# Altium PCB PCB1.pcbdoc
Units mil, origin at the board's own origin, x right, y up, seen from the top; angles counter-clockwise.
Board outline 3300 x 2850 mil, 2 copper layers (Top Layer, Bottom Layer), stack 62.206 mil thick; 39 components, 28 nets, 169 pads, 54 vias.
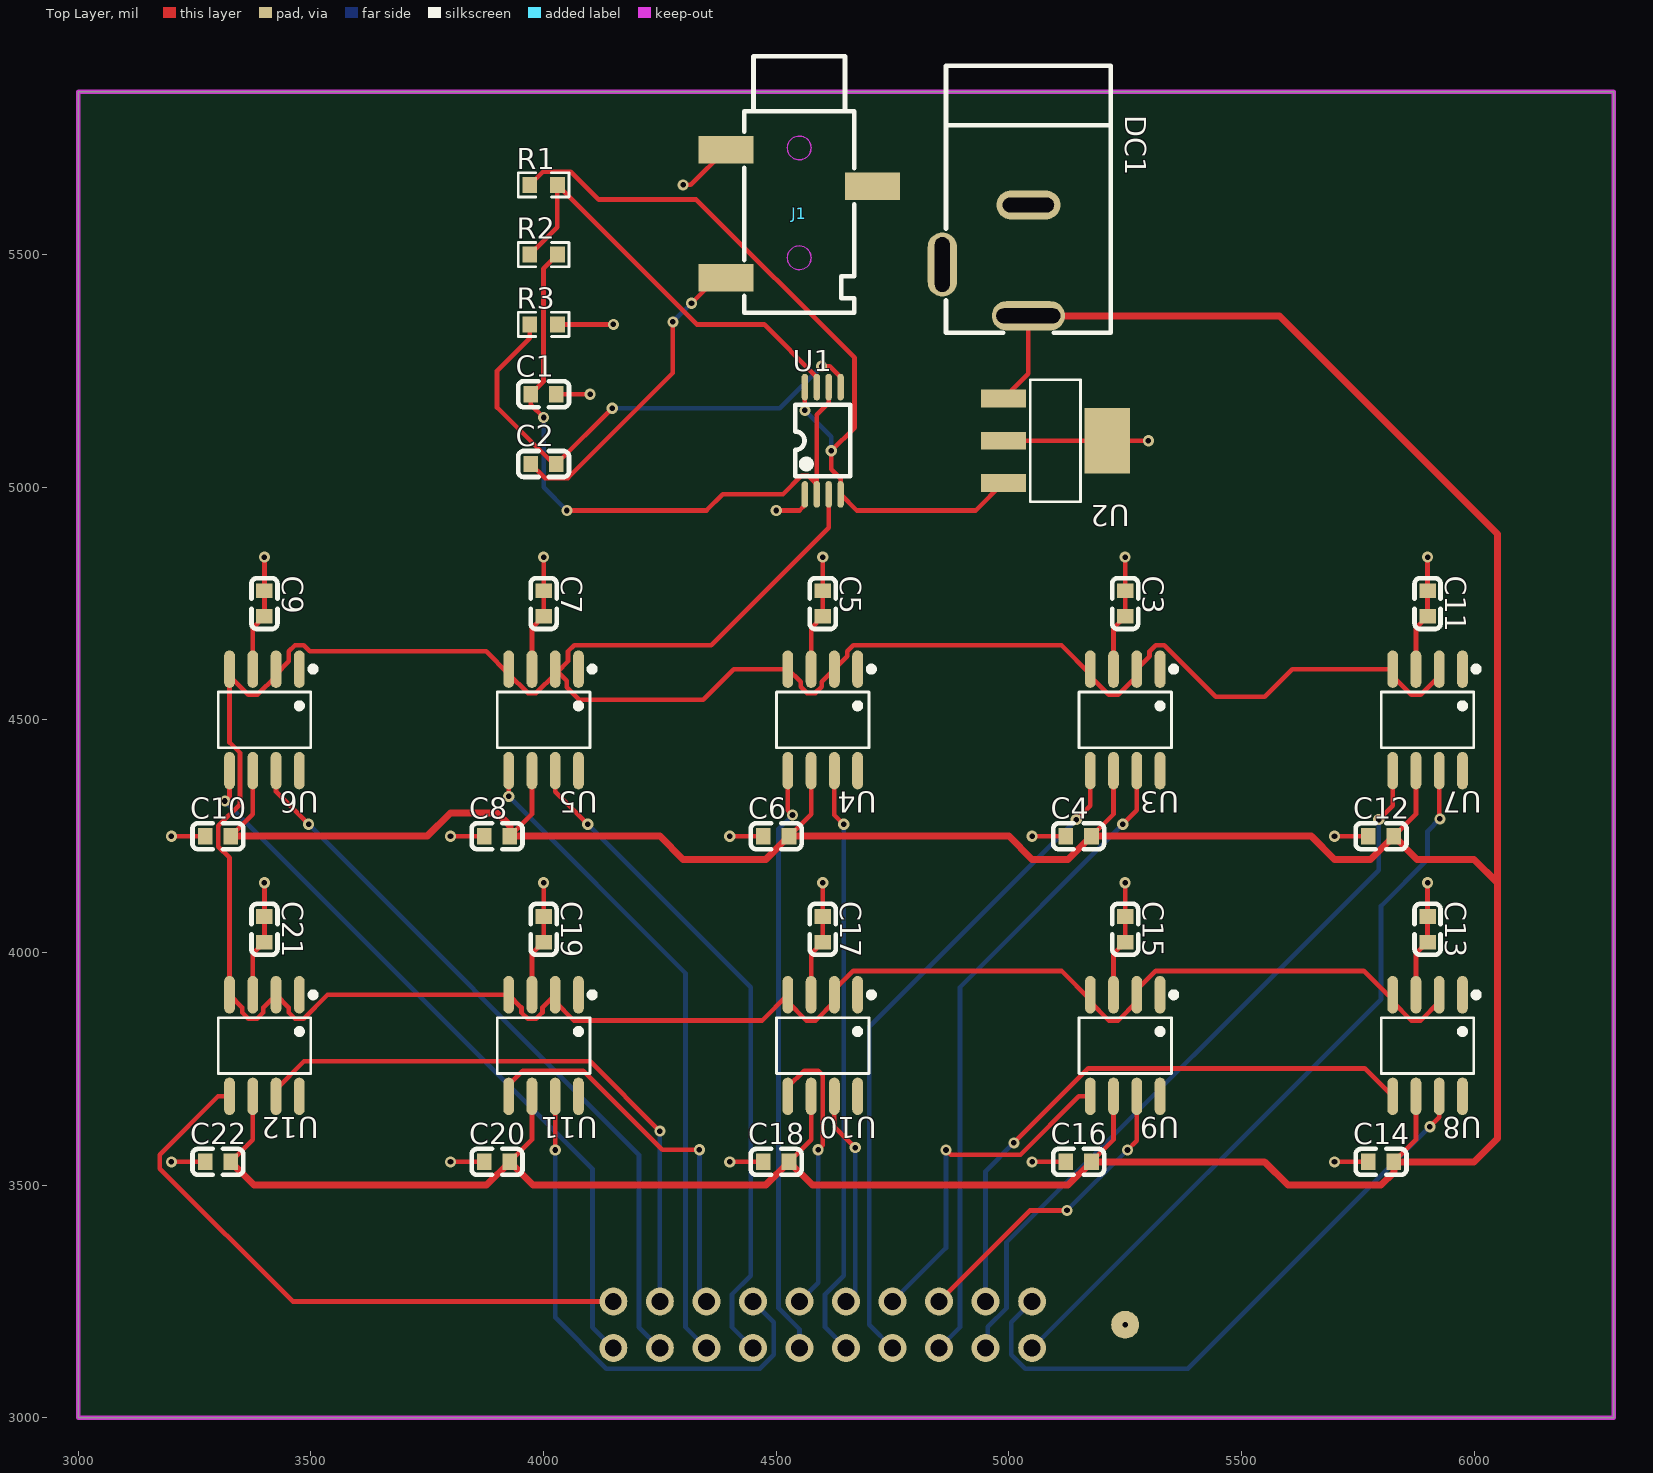
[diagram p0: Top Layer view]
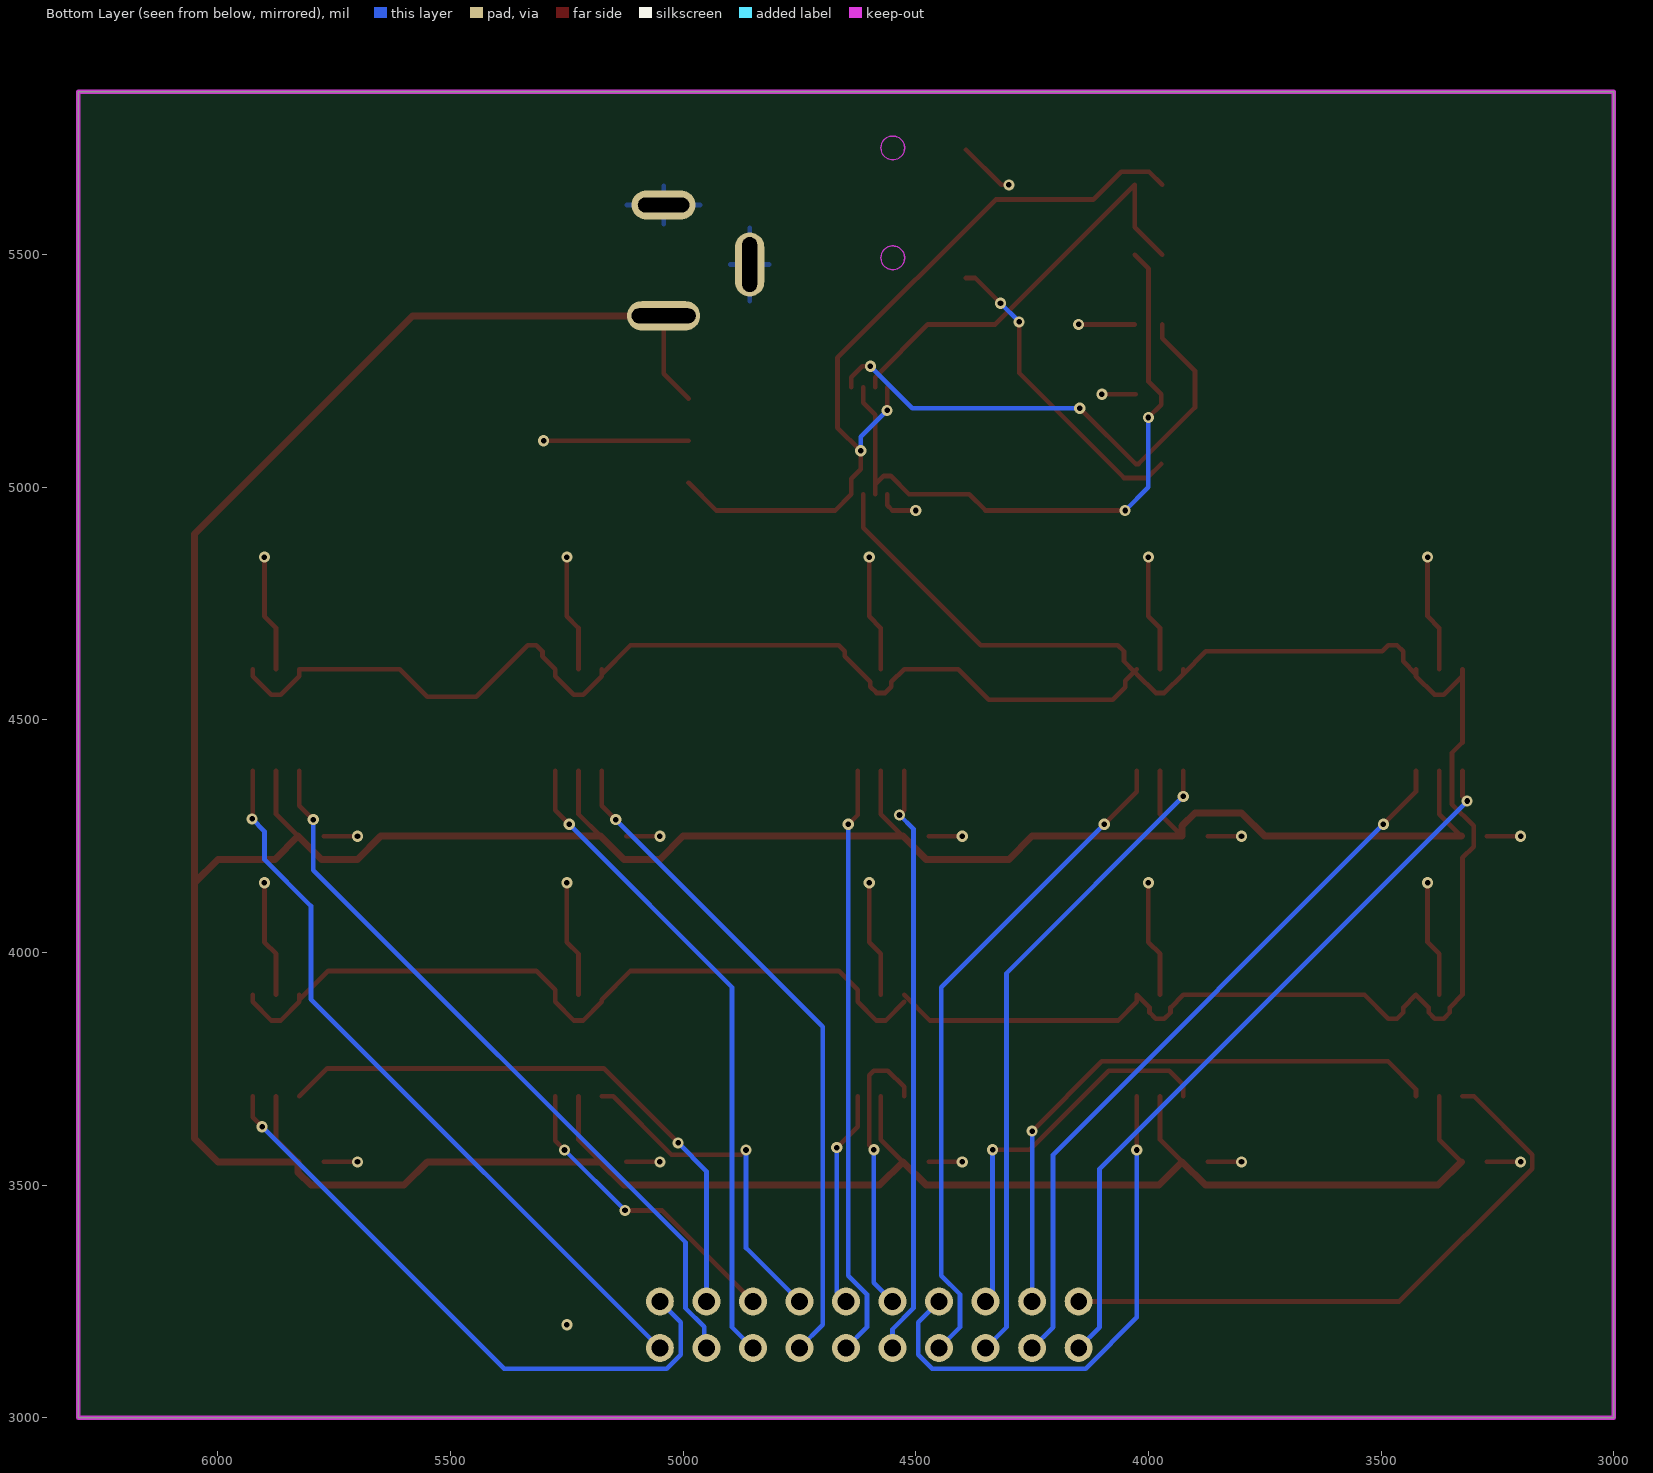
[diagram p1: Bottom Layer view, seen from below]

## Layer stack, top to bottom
Top Solder Mask Layer: solder mask 0.394, Dk 3.3
Top Layer: signal copper 1.379
Dielectric1: surface 59.449, FR4, Dk 4.5
Bottom Layer: signal copper 1.378
Bottom Solder Mask Layer: solder mask 0.394, Dk 3.3

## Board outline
3000,5850 6300,5850 6300,3000 3000,3000

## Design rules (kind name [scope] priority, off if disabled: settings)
BoardOutlineClearance copperThickness1oz [All] p0: genericclearance=10 ignorepadtopadclearanceinfootprint=FALSE except(0: Arc-SplitContinuation Track-SplitContinuation SMDPad-SplitContinuation THPad-SplitContinuation Via-SplitContinuation Fill-SplitContinuation Poly-SplitContinuation Region-SplitContinuation Text-SplitContinuation)
BoardOutlineClearance copperThickness2oz [All] p0: genericclearance=10 ignorepadtopadclearanceinfootprint=FALSE except(0: Arc-SplitContinuation Track-SplitContinuation SMDPad-SplitContinuation THPad-SplitContinuation Via-SplitContinuation Fill-SplitContinuation Poly-SplitContinuation Region-SplitContinuation Text-SplitContinuation)
BoardOutlineClearance otherClearance [All] p0: genericclearance=10 ignorepadtopadclearanceinfootprint=FALSE except(0: Arc-SplitContinuation Track-SplitContinuation SMDPad-SplitContinuation THPad-SplitContinuation Via-SplitContinuation Fill-SplitContinuation Poly-SplitContinuation Region-SplitContinuation Text-SplitContinuation)
Clearance copperThickness1oz [All] p1: gap=7 ignorepadtopadclearanceinfootprint=FALSE
Clearance copperThickness2oz [All] p1: gap=7 ignorepadtopadclearanceinfootprint=FALSE
Clearance otherClearance [All] p1: gap=7 ignorepadtopadclearanceinfootprint=FALSE
DiffPairsRouting differentialPair [All] p1: maxuncoupledlength=10 minlimit=6 maxlimit=Infinity mostfreqgap=6 toplayer_minwidth=5 toplayer_prefwidth=10 toplayer_maxwidth=100 bottomlayer_minwidth=5 bottomlayer_prefwidth=10 bottomlayer_maxwidth=100
PasteMaskExpansion pasteMaskExpansion [All] p1: expansion=0
PlaneConnect innerPlane [All] p1: planeconnectstyle=Relief reliefexpansion=20 reliefentries=4 reliefconductorwidth=10 reliefairgap=10
PolygonConnect copperRegion [All] p1: connectstyle=Relief reliefentries=4 reliefconductorwidth=10 polygonreliefangle="90 Angle" airgapwidth=10
RoutingVias viaSize [All] p1: viastyle="Through Hole" holewidth=12.0078 minholewidth=11.811 maxholewidth=248.0314 width=12.0078 minwidth=11.811 maxwidth=248.0314
SolderMaskExpansion solderMaskExpansion [All] p1: useseparateexpansions=TRUE expansion=2 expansionbottom=2
Width copperThickness1oz [All] p1: maxlimit=100 minlimit=5 preferedwidth=10
Width copperThickness2oz [All] p1: maxlimit=100 minlimit=8 preferedwidth=10

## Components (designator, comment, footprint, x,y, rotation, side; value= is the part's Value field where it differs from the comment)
C1 "" C0603 4000,5200 r0 top
C2 "" C0603 4000,5050 r0 top
C3 "" C0603 5250,4750 r270 top
C4 "" C0603 5150,4250 r0 top
C5 "" C0603 4600,4750 r270 top
C6 "" C0603 4500,4250 r0 top
C7 "" C0603 4000,4750 r270 top
C8 "" C0603 3900,4250 r0 top
C9 "" C0603 3400,4750 r270 top
C10 "" C0603 3300,4250 r0 top
C11 "" C0603 5900,4750 r270 top
C12 "" C0603 5800,4250 r0 top
C13 "" C0603 5900,4050 r270 top
C14 "" C0603 5800,3550 r0 top
C15 "" C0603 5250,4050 r270 top
C16 "" C0603 5150,3550 r0 top
C17 "" C0603 4600,4050 r270 top
C18 "" C0603 4500,3550 r0 top
C19 "" C0603 4000,4050 r270 top
C20 "" C0603 3900,3550 r0 top
C21 "" C0603 3400,4050 r270 top
C22 "" C0603 3300,3550 r0 top
DC1 "" DC-IN-TH_DC-005D-2.0-PU-SP 4949.51,5487.65 r270 top
J1 "" AUDIO-SMD_PJ-320B 4549.51,5587.65 r0 top
R1 "" R0603 4000,5650 r0 top
R2 "" R0603 4000,5500 r0 top
R3 "" R0603 4000,5350 r0 top
U1 "" TSSOP-8_L4.4-W3.0-P0.65-LS6.4-BL 4600,5100 r0 top
U2 "" SOT-223-4_L6.5-W3.5-P2.30-LS7.0-BR 5100,5100 r180 top
U3 "" SOIC-8_L4.9-W3.9-P1.27-LS6.0-BL 5250,4500 r180 top
U4 "" SOIC-8_L4.9-W3.9-P1.27-LS6.0-BL 4600,4500 r180 top
U5 "" SOIC-8_L4.9-W3.9-P1.27-LS6.0-BL 4000,4500 r180 top
U6 "" SOIC-8_L4.9-W3.9-P1.27-LS6.0-BL 3400,4500 r180 top
U7 "" SOIC-8_L4.9-W3.9-P1.27-LS6.0-BL 5900,4500 r180 top
U8 "" SOIC-8_L4.9-W3.9-P1.27-LS6.0-BL 5900,3800 r180 top
U9 "" SOIC-8_L4.9-W3.9-P1.27-LS6.0-BL 5250,3800 r180 top
U10 "" SOIC-8_L4.9-W3.9-P1.27-LS6.0-BL 4600,3800 r180 top
U11 "" SOIC-8_L4.9-W3.9-P1.27-LS6.0-BL 4000,3800 r180 top
U12 "" SOIC-8_L4.9-W3.9-P1.27-LS6.0-BL 3400,3800 r180 top

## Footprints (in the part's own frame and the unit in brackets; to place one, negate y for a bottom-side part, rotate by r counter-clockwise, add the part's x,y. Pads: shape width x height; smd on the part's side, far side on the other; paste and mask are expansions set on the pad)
AUDIO-SMD_PJ-320B [mm]
  rect 3x1.5 smd: 1(-4,3.5) 2(4,1.5) 3(-4,-3.5)
  Board Outline Layer circle w0.003: c0,3.6 r0.65
  Board Outline Layer circle w0.003: c0,-2.4 r0.65
  Board Outline Layer region: 0.65,3.6 0.586,3.318 0.405,3.092 0.145,2.966 -0.145,2.966 -0.405,3.092 -0.586,3.318 -0.65,3.6 -0.65,3.6 -0.586,3.882 -0.405,4.108 -0.145,4.234 0.145,4.234 0.405,4.108 0.586,3.882 0.65,3.6
  Board Outline Layer region: 0.65,3.6 0.586,3.318 0.405,3.092 0.145,2.966 -0.145,2.966 -0.405,3.092 -0.586,3.318 -0.65,3.6 -0.65,3.6 -0.586,3.882 -0.405,4.108 -0.145,4.234 0.145,4.234 0.405,4.108 0.586,3.882 0.65,3.6
  Board Outline Layer region: 0.65,-2.4 0.586,-2.682 0.405,-2.908 0.145,-3.034 -0.145,-3.034 -0.405,-2.908 -0.586,-2.682 -0.65,-2.4 -0.65,-2.4 -0.586,-2.118 -0.405,-1.892 -0.145,-1.766 0.145,-1.766 0.405,-1.892 0.586,-2.118 0.65,-2.4
  Board Outline Layer region: 0.65,-2.4 0.586,-2.682 0.405,-2.908 0.145,-3.034 -0.145,-3.034 -0.405,-2.908 -0.586,-2.682 -0.65,-2.4 -0.65,-2.4 -0.586,-2.118 -0.405,-1.892 -0.145,-1.766 0.145,-1.766 0.405,-1.892 0.586,-2.118 0.65,-2.4
  silkscreen extent -3,-5.4 3,8.6
C0603 [mm]
  rect 0.8x0.9 smd: 1(-0.7,0) 2(0.7,0)
  silkscreen extent -1.39,-0.71 1.39,0.71
DC-IN-TH_DC-005D-2.0-PU-SP [mm]
  oval 3.5x1.6 hole 0.8 slot 3 at 0 deg: 2(0.225,-2.35)
  oval 1.6x3.5 hole 0.8 slot 2.8 at 90 deg: 3(-3.025,2.35)
  oval 1.6x4 hole 0.8 slot 3.5 at 90 deg: 4(3.025,2.35)
  silkscreen extent -10.62,-2.15 3.96,6.85
R0603 [mil]
  rect 31.75x34.02 smd: 1(-29.66,0) 2(29.66,0)
  silkscreen extent -55,-26 55,26
SOIC-8_L4.9-W3.9-P1.27-LS6.0-BL [mm]
  oval 0.588x2.045 smd: 1(-1.905,-2.772) 2(-0.635,-2.772) 3(0.635,-2.772) 4(1.905,-2.772) 5(1.905,2.772) 6(0.635,2.772) 7(-0.635,2.772) 8(-1.905,2.772)
  silkscreen extent -2.8,-2.92 2.53,1.52
SOT-223-4_L6.5-W3.5-P2.30-LS7.0-BR [mm]
  rect 2.47x0.98 smd: 1(2.835,-2.3) 2(2.835,0) 3(2.835,2.3)
  rect 2.47x3.6 smd: 4(-2.835,0)
  silkscreen extent -1.37,-3.33 1.37,3.33
TSSOP-8_L4.4-W3.0-P0.65-LS6.4-BL [mil]
  oval 13.9x57.24 smd: 1(-38.39,-115.24) 2(-12.79,-115.24) 3(12.8,-115.24) 4(38.39,-115.24) 5(38.39,115.24) 6(12.8,115.24) 7(-12.79,115.24) 8(-38.39,115.24)
  silkscreen extent -59,-76 59,77

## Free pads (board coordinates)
  round 60 hole 36: 1(5050,3150) 2(4950,3150) 3(4850,3150) 4(4750,3150) 5(4650,3150) 6(4550,3150) 7(4450,3150) 8(4350,3150) 9(4250,3150) 10(4150,3150) 11(5050,3250) 12(4950,3250) 13(4850,3250) 14(4750,3250) 15(4650,3250) 16(4550,3250) 17(4450,3250) 18(4350,3250) 19(4250,3250) 20(4150,3250)
  round 60 smd: 1(5250,3200)

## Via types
v1: diameter 24.02, hole 12.01, Top Layer to Bottom Layer, 54 vias

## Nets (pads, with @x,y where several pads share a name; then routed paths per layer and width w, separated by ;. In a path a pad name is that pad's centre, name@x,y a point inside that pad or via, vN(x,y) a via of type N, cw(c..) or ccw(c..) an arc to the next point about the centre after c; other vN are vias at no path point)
$1N2: C2.2 R3.1 U1.5 | length 1114.5
  Top Layer w10: R3.1 3970.34,5320.34 3900,5250 3900,5171.44 4021.44,5050 C2.2 v1(4147.56,5170) ; v1(4597.56,5260) 4615.08,5260 4638.39,5236.68 U1.5
  Bottom Layer w10: v1(4147.56,5170) 4507.56,5170 v1(4597.56,5260)
$1N4: C2.1 J1.3 | length 674.5
  Top Layer w10: C2.1 4002.44,5020 4052.44,5020 4277.98,5245.54 v1(4277.98,5355.54) ; v1(4317.98,5395.54) 4372.3,5449.85 J1.3
  Bottom Layer w10: v1(4277.98,5355.54) v1(4317.98,5395.54)
$1N7: R1.2 R2.1 U1.7 | length 1015.4
  Top Layer w10: R2.1 4029.66,5559.32 ; U1.7 4587.21,5236.67 4473.88,5350 4329.66,5350 R1.2 ; 4029.66,5559.32 R1.2 ; 4029.66,5559.32 R1.2
$1N8: C1.1 R2.2 U1.2 U1.6 | length 1707.6
  Top Layer w10: v1(4000,5150) 3972.44,5177.56 C1.1 3999.66,5227.22 ; v1(4050,4950) 4350,4950 4384.76,4984.76 4514.58,4984.76 4554.18,5024.37 4569.04,5024.37 U1.2@4587.21,5006.2 ; U1.2 U1.2@4587.21,5006.2 ; U1.6 4612.8,5181.62 4587.21,5156.03 U1.2@4587.21,5006.2 ; 3999.66,5227.22 4000,5227.56 4000,5470.34 ; 3999.66,5227.22 3999.66,5470 4000,5470.34 ; 4000,5470.34 R2.2 4000,5470.34
  Bottom Layer w10: v1(4000,5150) 4000,5000 v1(4050,4950)
$1N9: R1.1 U1.4 U1.8 U2.3 | length 1747.5
  Top Layer w10: R1.1 3998.72,5678.38 4058.39,5678.38 4118.39,5618.38 4328.39,5618.38 4668.39,5278.38 4668.39,5128.38 v1(4618.39,5078.38) 4618.39,5038.38 4638.39,5018.38 U1.4 4673.15,4950 4928.94,4950 U2.3 ; v1(4561.61,5165.16) U1.8
  Bottom Layer w10: v1(4561.61,5165.16) 4618.39,5108.38 v1(4618.39,5078.38)
GND: C1.2 C3.1 C3.2 C4.1 C5.1 C5.2 C6.1 C7.1 C7.2 C8.1 C9.1 C9.2 C10.1 C11.1 C11.2 C12.1 C13.1 C13.2 C14.1 C15.1 C15.2 C16.1 C17.1 C17.2 C18.1 C19.1 C19.2 C20.1 C21.1 C21.2 C22.1 DC1.2 DC1.3 J1.1 pad.1@5250,3200 R3.2 U1.1 U2.2 U2.4 U3.3 U4.3 U5.3 U6.3 U7.3 U8.3 U9.3 U10.3 U11.3 U12.3 | length 3953.7
  Top Layer w10: v1(3200,3550) C22.1 ; v1(3200,4250) C10.1 ; U12.3 3375,3997.44 C21.2 C21.1 v1(3400,4150) ; U6.3 3375,4697.44 C9.2 C9.1 v1(3400,4850) ; v1(3800,3550) C20.1 ; v1(3800,4250) C8.1 ; U11.3 3975,3997.44 C19.2 C19.1 v1(4000,4150) ; U5.3 3975,4697.44 C7.2 C7.1 v1(4000,4850) ; C1.2 v1(4100,5200) ; R3.2 v1(4150,5350) ; v1(4300,5650) 4316.59,5650 J1.1 ; v1(4400,3550) C18.1 ; v1(4400,4250) C6.1 ; v1(4500,4950) 4550,4950 4561.61,4961.61 U1.1 ; U10.3 4575,3997.44 C17.2 C17.1 v1(4600,4150) ; U4.3 4575,4697.44 C5.2 C5.1 v1(4600,4850) ; U2.2 U2.4 v1(5300,5100) ; v1(5050,3550) C16.1 ; v1(5050,4250) C4.1 ; U9.3 5225,3997.44 C15.2 C15.1 v1(5250,4150) ; U3.3 5225,4697.44 C3.2 C3.1 v1(5250,4850) ; v1(5700,3550) C14.1 ; v1(5700,4250) C12.1 ; U8.3 5875,3997.44 C13.2 C13.1 v1(5900,4150) ; U7.3 5875,4697.44 C11.2 C11.1 v1(5900,4850)
  other v1: 5250,3200
OUT1: pad.1@5050,3150 U7.7 | length 1604.5
  Top Layer w10: U7.7@5925,4390.85 5925,4288.61 v1(5926.51,4287.1)
  Bottom Layer w10: pad.1@5050,3150 5800,3900 5800,4100 5900,4200 5900,4260.59 v1(5926.51,4287.1)
OUT2: pad.2 U7.5 | length 1603.3
  Top Layer w10: v1(5795,4285.59) 5825,4315.59 U7.5@5825,4390.85
  Bottom Layer w10: pad.2 4955,3155 4955,3195.6 4995,3235.6 4995,3376.86 5795,4176.85 v1(5795,4285.59)
OUT3: pad.3 U3.7 | length 1416.9
  Top Layer w10: v1(5245,4275.59) 5275,4305.59 U3.7@5275,4390.85
  Bottom Layer w10: pad.3 4895,3195 4895,3925.6 v1(5245,4275.59)
OUT4: pad.4 U3.5 | length 1458.3
  Top Layer w10: v1(5145,4285.59) 5175,4315.59 U3.5@5175,4390.85
  Bottom Layer w10: pad.4 4700,3200 4700,3840.6 v1(5145,4285.59)
OUT5: pad.5 U4.7 | length 1284.3
  Top Layer w10: U4.7@4625,4390.85 4625,4295.59 v1(4645,4275.59)
  Bottom Layer w10: v1(4645,4275.59) 4645,3305.6 4605,3265.6 4605,3195 pad.5
OUT6: pad.6 U4.5 | length 1276.1
  Top Layer w10: U4.5@4525,4390.85 4525,4305.59 v1(4535,4295.59)
  Bottom Layer w10: v1(4535,4295.59) 4505,4265.59 4505,3235.6 4550,3190.6 pad.6
OUT7: pad.7 U5.7 | length 1450
  Top Layer w10: U5.7@4025,4390.85 4025,4345.59 v1(4095,4275.59)
  Bottom Layer w10: v1(4095,4275.59) 4445,3925.6 4445,3305.6 4405,3265.6 4405,3195 pad.7
OUT8: pad.8 U5.5 | length 1416.9
  Top Layer w10: v1(3925,4335.59) U5.5@3925,4390.85
  Bottom Layer w10: v1(3925,4335.59) 4305,3955.6 4305,3195 pad.8
OUT9: pad.9 U6.7 | length 1582.6
  Top Layer w10: U6.7@3425,4390.85 3425,4345.59 v1(3495,4275.59)
  Bottom Layer w10: v1(3495,4275.59) 4205,3565.6 4205,3195 pad.9
OUT10: pad.10 U6.5 | length 1590.9
  Top Layer w10: v1(3315,4325.59) 3325,4335.59 U6.5@3325,4390.85
  Bottom Layer w10: v1(3315,4325.59) 4105,3535.6 4105,3195 pad.10
OUT11: pad.11 U8.7 | length 1334.4
  Top Layer w10: v1(5905,3625.6) 5925,3645.6 U8.7@5925,3690.85
  Bottom Layer w10: pad.11 5005,3205 5005,3135.6 5035,3105.6 5385,3105.6 v1(5905,3625.6)
OUT12: pad.12 U8.5 | length 1271.3
  Top Layer w10: v1(5010.85,3590.85) 5170.85,3750.85 5765,3750.85 U8.5@5825,3690.85
  Bottom Layer w10: pad.12 4950,3530 v1(5010.85,3590.85)
OUT13: pad.13 U9.7 | length 663.4
  Top Layer w10: pad.13 5045.6,3445.6 v1(5125,3445.6) ; v1(5255,3575.6) 5275,3595.6 U9.7@5275,3690.85
  Bottom Layer w10: v1(5125,3445.6) v1(5255,3575.6)
OUT14: pad.14 U9.5 | length 739.3
  Top Layer w10: v1(4865,3575.6) 4875,3565.6 5025,3565.6 5150.25,3690.85 U9.5@5175,3690.85
  Bottom Layer w10: pad.14 4865,3365 v1(4865,3575.6)
OUT15: pad.15 U10.7 | length 467.8
  Top Layer w10: U10.7@4625,3690.85 4625,3625.6 v1(4670,3580.6)
  Bottom Layer w10: pad.15 4670,3270 v1(4670,3580.6)
OUT16: pad.16 U10.5 | length 620.7
  Top Layer w10: U10.5@4525,3690.85 4525,3711.11 4560,3746.11 4590,3746.11 4600,3736.11 4600,3586.11 v1(4590,3576.11)
  Bottom Layer w10: pad.16 4590,3290 v1(4590,3576.11)
OUT17: pad.17 U11.7 | length 1136.3
  Top Layer w10: v1(4025,3575.6) U11.7@4025,3690.85
  Bottom Layer w10: v1(4025,3575.6) 4025,3215.6 4135,3105.6 4465,3105.6 4495,3135.6 4495,3205 pad.17
OUT18: pad.18 U11.5 | length 850.4
  Top Layer w10: U11.5@3925,3690.85 3925,3716.11 3955,3746.11 4085,3746.11 4255,3576.11 v1(4335,3576.11)
  Bottom Layer w10: v1(4335,3576.11) 4335,3265 pad.18
OUT19: pad.19 U12.7 | length 1293.3
  Top Layer w10: U12.7@3425,3690.85 3425,3706.11 3485,3766.11 4100,3766.11 v1(4250,3616.11)
  Bottom Layer w10: pad.19 v1(4250,3616.11)
OUT20: pad.20 U12.5 | length 1325.2
  Top Layer w10: U12.5@3325,3690.85 3300.26,3690.85 3175,3565.6 3175,3535.6 3460.6,3250 pad.20
PWM: U1.3 U3.2 U3.4 U4.2 U4.4 U5.2 U5.4 U6.2 U6.4 U7.2 U7.4 U8.2 U8.4 U9.2 U9.4 U10.2 U10.4 U11.2 U11.4 U12.2 U12.4 | length 7785.3
  Top Layer w10: U6.2@3425,4609.15 U6.2@3425,4598.57 ; U5.4@3925,4609.15 U5.4@3925,4598.56 ; U5.2@4025,4598.57 3984.34,4557.91 3965.66,4557.91 U5.4@3925,4598.56 ; U5.2 U5.2@4030.29,4603.86 ; U10.4@4525,3893.89 4565,3853.89 4585,3853.89 4625,3893.89 U10.2 4625,3919.73 4665.66,3960.39 5113.18,3960.39 5175,3898.57 5175,3893.89 5215,3853.89 5235,3853.89 5275,3893.89 U9.2 5275,3919.73 5315.66,3960.39 5763.18,3960.39 U8.4@5825,3898.56 ; U10.4 4469.74,3853.89 4065,3853.89 4025,3893.89 4025,3909.15 3997.56,3881.71 3997.56,3871.12 3984.34,3857.91 3965.66,3857.91 3952.44,3871.12 3952.44,3881.71 U11.4 3535.58,3909.15 3484.34,3857.91 3465.66,3857.91 3452.44,3871.12 3452.44,3881.71 U12.2 3397.56,3881.71 3397.56,3871.12 3384.34,3857.91 3365.66,3857.91 3352.44,3871.12 3352.44,3881.71 U12.4 3325,4203.56 3300.83,4227.73 3300.83,4272.27 3347.56,4319 3347.56,4428.88 3325,4451.43 U6.4 3325,4593.89 3365,4553.89 3385,4553.89 3425,4593.89 U6.2@3425,4598.57 ; U1.3 4612.8,4912.8 4360.39,4660.39 4065.66,4660.39 4052.44,4647.18 4052.44,4626.01 U5.2@4030.29,4603.86 ; U3.4@5175,4609.15 U3.4@5175,4598.57 ; U8.4 U8.4@5825,3898.56 ; U8.2 5925,3893.89 5885,3853.89 5865,3853.89 5825,3893.89 U8.4@5825,3898.56 ; U7.2@5925,4609.15 5925,4593.89 5885,4553.89 5865,4553.89 5825,4593.89 5825,4609.15 5609.15,4609.15 5550,4550 5444.73,4550 5334.34,4660.39 5315.66,4660.39 5302.44,4647.18 5302.44,4636.59 U3.2 5275,4593.89 5235,4553.89 5215,4553.89 5175,4593.89 U3.4@5175,4598.57 ; U6.2@3425,4598.57 3452.44,4626.01 3452.44,4647.18 3465.66,4660.39 3484.34,4660.39 3497.56,4647.18 3876.39,4647.18 U5.4@3925,4598.56 ; U5.2@4030.29,4603.86 4050,4584.15 4050,4570.01 4077.08,4542.93 4342.93,4542.93 4350,4550 4409.15,4609.15 4525,4609.15 4552.44,4581.71 4552.44,4571.12 4565.66,4557.91 4584.34,4557.91 4597.56,4571.12 4597.56,4581.71 U4.2 4652.44,4636.59 4652.44,4647.18 4665.66,4660.39 5113.18,4660.39 U3.4@5175,4598.57
VDD: C4.2 C6.2 C8.2 C10.2 C12.2 C14.2 C16.2 C18.2 C20.2 C22.2 DC1.4 U2.1 U3.6 U4.6 U5.6 U6.6 U7.6 U8.6 U9.6 U10.6 U11.6 U12.6 | length 10746.9
  Top Layer w10: C22.2 3375,3597.44 ; C10.2 3375,4297.44 U6.6 ; C20.2 3975,3597.44 U11.6 ; C8.2 3975,4297.44 U5.6 ; C6.2 4575,4297.44 U4.6 ; U2.1 5042.03,5244.19 DC1.4 ; C14.2 5875,3597.44 U8.6 ; C12.2 5875,4297.44 U7.6 ; 3375,3597.44 3375,3690.85 3375,3597.44 ; 4575,3597.44 U10.6 4575,3597.44 ; 4575,3597.44 C18.2 4575,3597.44 ; 5225,3597.44 U9.6 5225,3597.44 ; 5225,3597.44 C16.2 5225,3597.44 ; 5225,4297.44 C4.2 5225,4297.44 ; 5225,4297.44 U3.6 5225,4297.44
  Top Layer w15: C22.2 3377.56,3500 3877.56,3500 C20.2 3977.56,3500 4477.56,3500 C18.2 4577.56,3500 5127.56,3500 C16.2 5550,3550 5600,3500 5800,3500 5827.56,3527.56 C14.2 6000,3550 6050,3600 6050,4150 ; C10.2 3750,4250 3800,4300 3900,4300 3927.56,4272.44 C8.2 4250,4250 4300,4200 4477.56,4200 C6.2 5000,4250 5050,4200 5127.56,4200 C4.2 5650,4250 5700,4200 5777.56,4200 C12.2 5877.56,4200 6000,4200 6050,4150 ; DC1.4 5581.45,5368.55 6050,4900 6050,4150
pads on no net: J1.2 U3.1 U3.8 U4.1 U4.8 U5.1 U5.8 U6.1 U6.8 U7.1 U7.8 U8.1 U8.8 U9.1 U9.8 U10.1 U10.8 U11.1 U11.8 U12.1 U12.8

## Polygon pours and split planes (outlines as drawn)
GND on Bottom Layer (solid, remove dead copper, pour order 0): 3150,5750 6150,5750 6150,3100 3150,3100

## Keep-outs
Board Outline Layer:
  the board outline again, w10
